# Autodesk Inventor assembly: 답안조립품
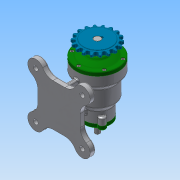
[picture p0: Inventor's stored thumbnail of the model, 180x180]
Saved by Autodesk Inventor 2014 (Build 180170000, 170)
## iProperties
Created: 2017-03
Part Number: 답안조립품
Document SubType Name: Assembly
Designer: 703
Author: 703
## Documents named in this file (14)
- C:\Users\703\Desktop\470307V1006\답안조립품.iam
- C:\Users\703\Desktop\470307V1006\본체.ipt
- C:\Users\703\Desktop\470307V1006\앞커버.ipt
- C:\Users\703\Desktop\470307V1006\베어링-6203.ipt
- C:\Users\703\Desktop\470307V1006\뒤커버.ipt
- C:\Users\703\Desktop\470307V1006\오일 실 17 30 8.ipt
- C:\Users\703\Desktop\470307V1006\오일 실 10 20 7.ipt
- C:\Users\703\Desktop\470307V1006\축.ipt
- C:\Users\703\Desktop\470307V1006\베어링-6200.ipt
- C:\Users\703\Desktop\470307V1006\키5x5.ipt
- C:\Users\703\Desktop\470307V1006\스프로킷.ipt
- C:\Users\703\Desktop\470307V1006\볼트 M4 x 12.ipt
- C:\Users\703\Desktop\470307V1006\볼트 M5 x 10.ipt
- 볼트 M5 x 10.ipt
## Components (9 placed, 1 different names)
1. ISO 4762 M4 x 12:1
2. ISO 4762 M4 x 12:2
3. ISO 4762 M4 x 12:3
4. ISO 4762 M4 x 12:4
5. ISO 4762 M4 x 12:5
6. ISO 4762 M4 x 12:6
7. ISO 4762 M4 x 12:7
8. ISO 4762 M4 x 12:8
9. ISO 4762 M4 x 12:9
